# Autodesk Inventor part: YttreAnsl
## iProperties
Shininess: 20.0
Length Units: 11269
Angle Units: 11279
Time Units: 11290
Mass Units: 11283
Length Display Precision: 3
Angle Display Precision: 2
Compacted: True
Company: Autodesk EMEA
Created: 2000-11
Part Number: YttreAnsl
Material: Steel, Mild
Description: Coupling
Document SubType Name: Modeling
Designer: Franz Kaltseis
Density: 0.0
Volumn: 0.0
Area: 0.0
PropertySet Name: Model Information
Control State: 0
Master: False
Checked Out: False
Title: Koppling
Author: Franz Kaltseis
